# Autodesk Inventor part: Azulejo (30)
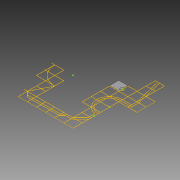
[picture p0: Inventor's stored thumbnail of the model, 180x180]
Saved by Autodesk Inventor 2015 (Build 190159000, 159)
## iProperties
Created: 2015-04
Part Number: Azulejo (30)
Material: Genérico
Document SubType Name: Modeling
Designer: Felipe
Density: 1 g/cm^3
Appearance: Padrão
Author: Felipe
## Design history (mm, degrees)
sketch "Sketch1"
  geometry: L1 (-1510, -7490)-(-1510, -6010); L2 (-3010, -1490)-(-3010, -10); L3 (-2990, 10)-(-1510, 10); L4 (-1510, -10)-(-2990, -10); L5 (-1510, -1490)-(-1510, -10); L6 (-1490, -10)-(-1490, -1490); L7 (-1490, -1490)-(-10, -1490); L8 (-10, -1510)-(-1490, -1510); L9 (-10, -2990)-(-10, -1510); L10 (-10, -5990)-(-10, -4510); L11 (-1490, -7490)-(-10, -7490); L12 (4490, -6010)-(3010, -6010); L13 (10, -1510)-(10, -2990); L14 (10, -3010)-(10, -4490); L15 (10, -4510)-(10, -5990); L16 (10, -5990)-(1490, -5990); L17 (1490, -6010)-(10, -6010); L18 (10, -7490)-(1490, -7490); L19 (1510, -5990)-(2990, -5990); L20 (2990, -6010)-(1510, -6010); L21 (1510, -7490)-(2990, -7490); L22 (4490, 1510)-(4490, 2990); L23 (4490, 10)-(4490, 1490); L24 (4490, -1490)-(4490, -10); L25 (4490, -2990)-(4490, -1510); L26 (3010, -5990)-(4490, -5990); L27 (3010, -7490)-(4490, -7490); L28 (4510, 3010)-(5990, 3010); L29 (5990, 2990)-(4510, 2990); L30 (4510, 2990)-(4510, 1510); L31 (4510, 1510)-(5990, 1510); L32 (5990, 1510)-(5990, 1740.185); L33 (5990, 1760.2)-(5990, 2259.8); L34 (5990, 2279.815)-(5990, 2990); L35 (5990, 1490)-(4510, 1490); L36 (4510, 1490)-(4510, 10); L37 (4510, 10)-(5990, 10); L38 (5990, 10)-(5990, 1490); L39 (5975.983, -10)-(4510, -10); L40 (4510, -10)-(4510, -1490); L41 (5990, -1510)-(5782.897, -1510); L42 (5782.897, -1510)-(5688.66, -1510); L43 (5668.66, -1510)-(5482.895, -1510); L44 (5482.895, -1510)-(5388.656, -1510); L45 (5368.656, -1510)-(4510, -1510); L46 (4510, -1510)-(4510, -2990); L47 (4510, -2990)-(5975.983, -2990); L48 (5990, -2975.728)-(5990, -2837.377); L49 (5990, -2837.377)-(5990, -2536.247); L50 (5990, -2500.476)-(5990, -2317.632); L51 (5990, -2317.632)-(5990, -1510); L52 (5990, -3010)-(4510, -3010); L53 (5990, -4490)-(5990, -3010); L54 (4510, -5990)-(5990, -5990); L55 (5990, -5990)-(5990, -4510); L56 (4510, -7490)-(5990, -7490); L57 (5990, -7490)-(5990, -6310); L58 (5990, -6290)-(5990, -6010); L59 (7490, 4510)-(7490, 5990); L60 (6010, 3010)-(7490, 3010); L61 (7490, 3010)-(7490, 4490); L62 (7490, 2990)-(6010, 2990); L63 (6010, 2990)-(6010, 2279.815); L64 (6010, 2259.8)-(6010, 1760.2)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; A1 r 250 centre (6000, 2010) between (5990, 2259.8) and (5990, 1760.2); A2 r 250 centre (6000, 2010) between (6010, 1760.2) and (6010, 2259.8); A3 r 270 centre (6000, 2010) between (5990, 2279.815) and (5990, 1740.185); A4 r 270 centre (6000, 2010) between (6010, 1740.185) and (6010, 2279.815); A5 r 3010.017 centre (0, 0) between (-1490, -2615.358) and (-346.554, -2990); A6 r 2990.017 centre (0, 0) between (-1490, -2592.316) and (-10, -2990); A7 r 3010.017 centre (0, 0) between (-2603.863, -1510) and (-1510, -2603.863); A8 r 2990.017 centre (0, 0) between (-2580.717, -1510) and (-1510, -2580.717); A9 r 3010.017 centre (0, 0) between (-2990, -346.554) and (-2615.358, -1490); A10 r 2990.017 centre (0, 0) between (-2990, -10) and (-2592.316, -1490); A11 r 2131.367 centre (7500, -1500) between (7490, 631.344) and (6010, 24.017); A12 r 2131.367 centre (7500, -1500) between (5975.983, -10) and (5368.656, -1490); A13 r 2131.367 centre (7500, -1500) between (5368.656, -1510) and (5975.983, -2990); A14 r 2131.367 centre (7500, -1500) between (6010, -3024.017) and (7190, -3608.703); A15 r 1831.367 centre (7500, -1500) between (7490.321, 331.342) and (6463.753, 10); A16 r 1831.367 centre (7500, -1500) between (6435.196, -10) and (6010, -435.196); A17 r 1831.367 centre (7500, -1500) between (5990, -463.753) and (5668.66, -1490); A18 r 1831.367 centre (7500, -1500) between (5668.66, -1510) and (5990, -2536.247); A19 r 1831.367 centre (7500, -1500) between (6010, -2564.804) and (6435.196, -2990); A20 r 1831.367 centre (7500, -1500) between (6463.753, -3010) and (7490, -3331.34); A21 r 2111.367 centre (7500, -1500) between (7490.047, 611.344) and (6024.272, 10); A22 r 2111.367 centre (7500, -1500) between (5990, -24.272) and (5388.656, -1490); A23 r 2111.367 centre (7500, -1500) between (5388.656, -1510) and (5990, -2975.728); A24 r 2111.367 centre (7500, -1500) between (6024.272, -3010) and (7210, -3591.357); A25 r 1811.367 centre (7500, -1500) between (7490.374, 311.342) and (6499.524, 10); A26 r 1811.367 centre (7500, -1500) between (6469.975, -10) and (6010, -469.975); A27 r 1811.367 centre (7500, -1500) between (5990, -499.524) and (5688.66, -1490); A28 r 1811.367 centre (7500, -1500) between (5688.66, -1510) and (5990, -2500.476); A29 r 1811.367 centre (7500, -1500) between (6010, -2530.025) and (6469.975, -2990); A30 r 1811.367 centre (7500, -1500) between (6499.524, -3010) and (7490, -3311.34); A31 r 449.871 centre (7499.449, -4060.672) between (7510, -4510.419) and (7521.546, -4510); 9 further points
  constraints: 698 end point, 64 point on circle, 31 centre point, 11 point on line, 1 other
extrude "Extrusion1" new body sketch "Sketch1" distance "d0" = 60; taper "d1" = 0 deg
extrude "Extrusion2" new body sketch "Sketch1" distance "d2" = 60; taper "d3" = 0 deg
body "Solid1"
body "Solid2"
